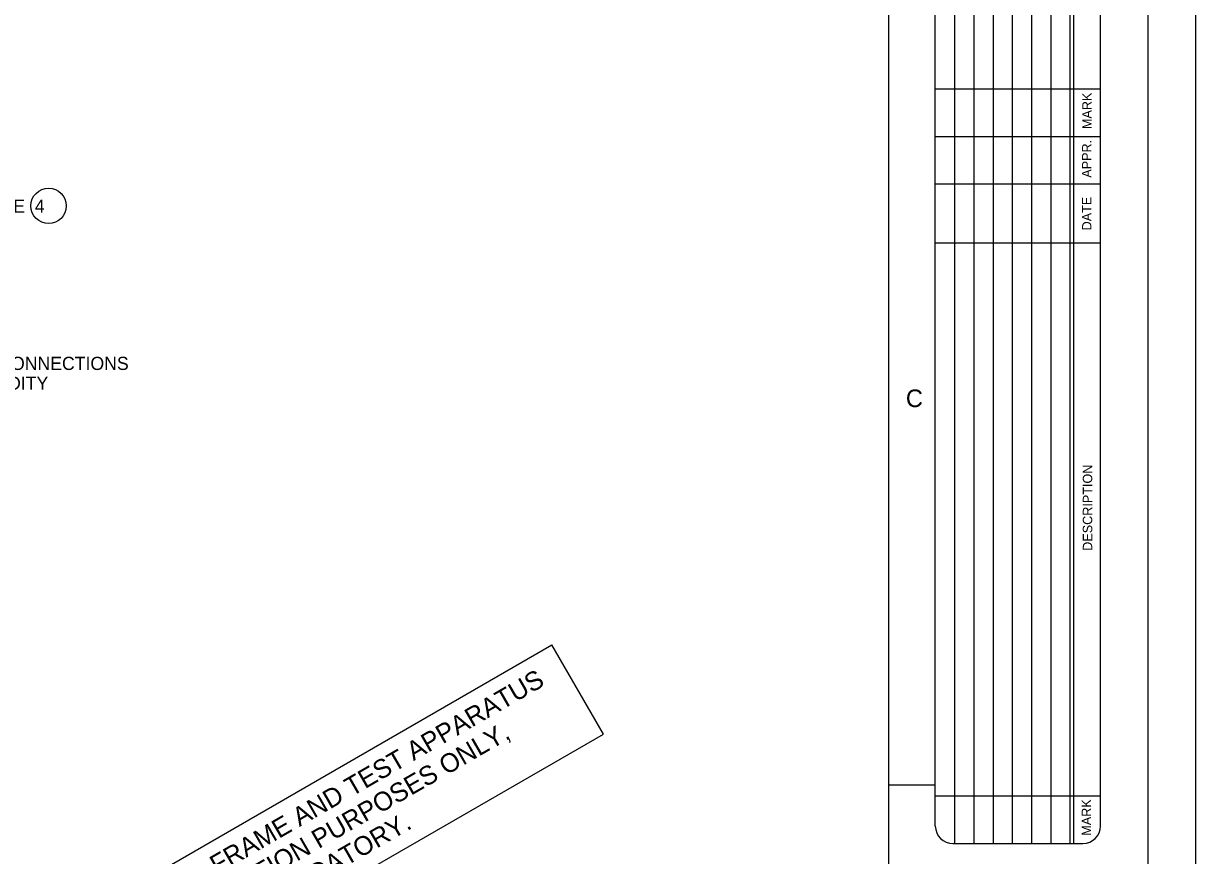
# Model space of a CAD drawing. Extents: x 22369.6 to 22413.6, y 22369.6 to 22403.6.
# Drawn here: x 22401.19 to 22413.62, y 22385.88 to 22394.7 of the extents above; entities that cross this region are included whole.
import ezdxf

# ---------------------------------------------------------------- set-up
doc = ezdxf.new("R2010")
doc.units = 0
for name, color, linetype in [('Level 1', 7, 'Continuous'), ('Level 10', 7, 'Continuous'), ('Level 4', 7, 'Continuous'), ('Level 7', 7, 'Continuous'), ('Level 9', 7, 'Continuous')]:
    doc.layers.add(name, color=color, linetype=linetype)

msp = doc.modelspace()

# ---------------------------------------------------------------- linework, layer by layer
at = {"layer": 'Level 1'}
for p, q in [((22411.066, 22401.001), (22411.066, 22386.001)), ((22411.27, 22401.001), (22411.27, 22386.001)), ((22411.474, 22401.001), (22411.474, 22386.001)), ((22411.678, 22401.001), (22411.678, 22386.001)), ((22411.882, 22401.001), (22411.882, 22386.001)), ((22412.086, 22401.001), (22412.086, 22386.001)), ((22412.29, 22401.001), (22412.29, 22386.001)), ((22412.326, 22401.001), (22412.326, 22386.001)), ((22412.614, 22393.501), (22410.862, 22393.501)), ((22412.426, 22386.001), (22411.049, 22386.001))]:
    msp.add_line(p, q, dxfattribs=at)
msp.add_lwpolyline([(22369.621, 22403.629), (22413.622, 22403.629), (22413.622, 22369.621), (22369.621, 22369.621)], close=True, dxfattribs=at)
for points in [[(22410.862, 22386.189), (22410.862, 22400.814)], [(22412.614, 22386.189), (22412.614, 22400.814)]]:
    msp.add_lwpolyline(points, dxfattribs=at)
for centre, start, end in [((22411.049, 22386.189), 180, 270), ((22412.426, 22386.189), 270, 0)]:
    msp.add_arc(centre, 0.187, start, end, dxfattribs=at)
at = {"layer": 'Level 10'}
for p, q in [((22401.298, 22384.937), (22406.796, 22388.112)), ((22407.343, 22387.165), (22406.796, 22388.112)), ((22401.844, 22383.991), (22407.343, 22387.165)), ((22410.37, 22386.625), (22410.862, 22386.625))]:
    msp.add_line(p, q, dxfattribs=at)
at = {"layer": 'Level 7'}
for p, q in [((22412.614, 22392.997), (22410.862, 22392.997)), ((22412.614, 22392.372), (22410.862, 22392.372)), ((22412.614, 22386.505), (22410.862, 22386.505))]:
    msp.add_line(p, q, dxfattribs=at)
msp.add_lwpolyline([(22412.614, 22394.005), (22410.862, 22394.005)], dxfattribs=at)
msp.add_circle((22401.459, 22392.768), 0.188, dxfattribs=at)
at = {"layer": 'Level 9'}
msp.add_line((22413.118, 22370.125), (22413.118, 22403.125), dxfattribs=at)
msp.add_lwpolyline([(22410.37, 22370.125), (22410.37, 22403.125)], dxfattribs=at)

# ---------------------------------------------------------------- texts
at = {"layer": 'Level 1'}
for s, p in [('MARK', (22412.52, 22393.583)), ('APPR.', (22412.518, 22393.067)), ('DATE', (22412.518, 22392.508)), ('DESCRIPTION', (22412.526, 22389.109)), ('MARK', (22412.514, 22386.086))]:
    msp.add_text(s, height=0.1, rotation=90, dxfattribs=at).set_placement(p)
msp.add_text('C', height=0.187, dxfattribs=at).set_placement((22410.55, 22390.633))
at = {"layer": 'Level 4'}
for s, p in [('SEE NOTE  4', (22400.262, 22392.695)), ('CROSS-CONNECTIONS', (22400.197, 22391.027)), ('FOR RIGIDITY', (22400.197, 22390.817))]:
    msp.add_text(s, height=0.14, dxfattribs=at).set_placement(p)
at = {"layer": 'Level 7'}
for s, p in [('THE LOADING FRAME AND TEST APPARATUS', (22401.61, 22384.729)), ('IS FOR ILLUSTRATION PURPOSES ONLY,', (22401.762, 22384.465)), ('UNLESS NOTED MANDATORY.', (22401.914, 22384.202))]:
    msp.add_text(s, height=0.2, rotation=30.0029, dxfattribs=at).set_placement(p)

doc.saveas('drawing.dxf')
